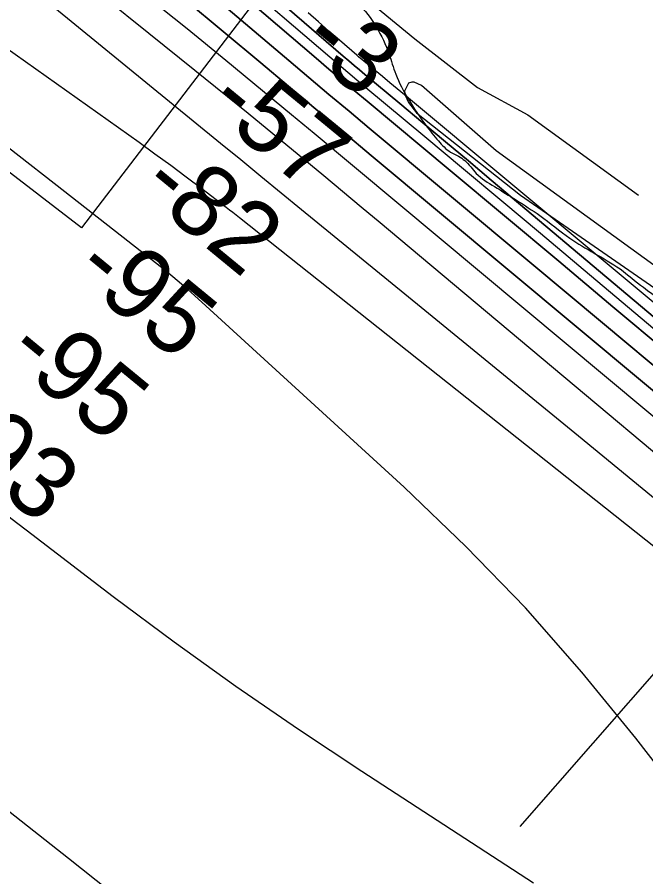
# Model space of a CAD drawing. Extents: x 3887375 to 3925618, y 296674 to 322633.
# Drawn here: x 3894086 to 3894675, y 313327 to 314133 of the extents above; entities that cross this region are included whole.
import ezdxf

# ---------------------------------------------------------------- set-up
doc = ezdxf.new("R2010")
doc.units = 0
for name, color, linetype in [('V-RIVR-EDGE', 7, 'Continuous'), ('V-RIVR-JETY', 7, 'Continuous'), ('V-RIVR-RANG', 7, 'Continuous'), ('V-RRAP-FSHR', 7, 'Continuous'), ('V-RRAP-RVMT', 7, 'Continuous'), ('V-TOPO-DPTH', 7, 'Continuous'), ('V-TOPO-MAJR', 7, 'Continuous'), ('V-TOPO-MINR', 7, 'Continuous')]:
    doc.layers.add(name, color=color, linetype=linetype)

msp = doc.modelspace()

# ---------------------------------------------------------------- linework, layer by layer
at = {"layer": 'V-RIVR-EDGE'}
msp.add_spline([(3894279.09, 314238.38), (3894300.17, 314224.38), (3894318.47, 314210.78), (3894328.81, 314199.99), (3894339.15, 314192.4), (3894356.26, 314181.59), (3894374.58, 314173.98), (3894382.14, 314170.37), (3894386.51, 314164.78), (3894397.24, 314152.8), (3894405.19, 314145.6), (3894434.57, 314098.11), (3894440.9, 314079.36), (3894452.8, 314055.82), (3894469.08, 314031.46), (3894480.99, 314016.69), (3894492.13, 314006.3), (3894499.69, 314002.3), (3894505.66, 313998.3), (3894516.39, 313986.31), (3894533.5, 313973.92), (3894554.19, 313961.11), (3894576.07, 313946.71), (3894604.32, 313925.52), (3894627, 313911.51), (3894651.27, 313896.71), (3894673.15, 313879.52), (3894705.37, 313857.52), (3894744.36, 313828.33), (3894786.92, 313794.75), (3894815.16, 313773.55), (3894843.81, 313753.56), (3894864.49, 313737.96), (3894892.75, 313720.36), (3894906.27, 313709.96), (3894922.58, 313696.37), (3894976.66, 313648.01), (3895020.01, 313612.44), (3895065.34, 313570.88), (3895097.95, 313544.49), (3895112.67, 313532.9), (3895136.93, 313510.92), (3895150.44, 313495.74), (3895161.57, 313484.16), (3895169.53, 313478.16), (3895202.12, 313443.41), (3895238.3, 313409.84), (3895281.24, 313368.29), (3895321.02, 313337.1), (3895346.88, 313317.51), (3895405.32, 313261.97), (3895426, 313241.2), (3895440.7, 313224.82), (3895449.44, 313212.44)], degree=3, dxfattribs=at)
at = {"layer": 'V-RIVR-JETY'}
msp.add_lwpolyline([(3894730.72, 313865.59), (3894535.14, 314007.56), (3894464.91, 314068.73), (3894458.11, 314071.75), (3894455.85, 314071.75), (3894452.82, 314071), (3894449.05, 314063.44), (3894449.8, 314059.67), (3894452.82, 314052.87), (3894460.38, 314043.05), (3894557.79, 313966.03), (3894695.99, 313870.12)], dxfattribs=at)
at = {"layer": 'V-RIVR-RANG'}
msp.add_line((3895031.53, 313915.92), (3894557.25, 313374.2), dxfattribs=at)
at = {"layer": 'V-RRAP-FSHR'}
msp.add_lwpolyline([(3894109.56, 314396.62), (3894271.96, 314268.33), (3894360.72, 314193.19), (3894458.91, 314112.56), (3894517.45, 314066.74), (3894564.66, 314041.08), (3894668.52, 313965.94)], dxfattribs=at)
at = {"layer": 'V-RRAP-RVMT'}
for p, q in [((3894338.29, 314186.44), (3894146.24, 313935.33)), ((3894146.24, 313935.33), (3894046.94, 314011.42))]:
    msp.add_line(p, q, dxfattribs=at)
at = {"layer": 'V-TOPO-DPTH'}
for points in [[(3895305.16, 313270.77), (3895231.56, 313335.34), (3895157.88, 313399.81), (3894995.3, 313541.84), (3894980.78, 313554.46), (3894966.21, 313567.04), (3894951.59, 313579.53), (3894936.92, 313591.98), (3894833.93, 313678.9), (3894767.68, 313734.72), (3894701.37, 313790.45), (3894634.96, 313846.06), (3894568.48, 313901.59), (3894415.94, 314028.77), (3894397.05, 314044.56), (3894378.18, 314060.37), (3894359.34, 314076.22), (3894340.52, 314092.09), (3893865.37, 314493.75)], [(3893865.37, 314493.75), (3894340.52, 314092.09), (3894359.34, 314076.22), (3894378.18, 314060.37), (3894397.05, 314044.56), (3894415.94, 314028.77), (3894568.48, 313901.59), (3894634.96, 313846.06), (3894701.37, 313790.45), (3894767.68, 313734.72), (3894833.93, 313678.9), (3894936.92, 313591.98), (3894951.59, 313579.53), (3894966.21, 313567.04), (3894980.78, 313554.46), (3894995.3, 313541.84), (3895157.88, 313399.81), (3895231.56, 313335.34), (3895305.16, 313270.77)], [(3895236.78, 313307.47), (3895189.92, 313348.65), (3895143.02, 313389.78), (3895096.04, 313430.82), (3895049.01, 313471.8), (3894970.56, 313540.04), (3894962.7, 313546.84), (3894954.82, 313553.63), (3894946.91, 313560.38), (3894938.99, 313567.11), (3894882.83, 313614.59), (3894846.78, 313645.01), (3894810.69, 313675.38), (3894774.54, 313705.68), (3894738.35, 313735.93), (3894417.97, 314003.19), (3894392.02, 314024.83), (3894366.08, 314046.48), (3894340.14, 314068.13), (3894314.2, 314089.78), (3894102.47, 314266.53)], [(3894102.47, 314266.53), (3894314.2, 314089.78), (3894340.14, 314068.13), (3894366.08, 314046.48), (3894392.02, 314024.83), (3894417.97, 314003.19), (3894738.35, 313735.93), (3894774.54, 313705.68), (3894810.69, 313675.38), (3894846.78, 313645.01), (3894882.83, 313614.59), (3894938.99, 313567.11), (3894946.91, 313560.38), (3894954.82, 313553.63), (3894962.7, 313546.84), (3894970.56, 313540.04), (3895049.01, 313471.8), (3895096.04, 313430.82), (3895143.02, 313389.78), (3895189.92, 313348.65), (3895236.78, 313307.47)], [(3894208.2, 314229.17), (3894366.18, 314094.17), (3894378.08, 314084.04), (3894390.01, 314073.95), (3894401.97, 314063.9), (3894413.96, 314053.88), (3894491.91, 313989), (3894542.85, 313946.52), (3894593.74, 313903.97), (3894644.56, 313861.34), (3894695.32, 313818.64), (3894934.83, 313616.82), (3894956.24, 313598.66), (3894977.59, 313580.42), (3894998.83, 313562.05), (3895019.99, 313543.6), (3895384.8, 313223.59)], [(3894208.2, 314229.17), (3894366.18, 314094.17), (3894378.08, 314084.04), (3894390.01, 314073.95), (3894401.97, 314063.9), (3894413.96, 314053.88), (3894491.91, 313989), (3894542.85, 313946.52), (3894593.74, 313903.97), (3894644.56, 313861.34), (3894695.32, 313818.64), (3894934.83, 313616.82), (3894956.24, 313598.66), (3894977.59, 313580.42), (3894998.83, 313562.05), (3895019.99, 313543.6), (3895384.8, 313223.59)], [(3895602.02, 313054.44), (3895044.64, 313545.3), (3895016.85, 313569.61), (3894988.95, 313593.79), (3894960.89, 313617.78), (3894932.72, 313641.65), (3894530.51, 313980.01), (3894509.11, 313997.98), (3894487.68, 314015.92), (3894466.23, 314033.83), (3894444.75, 314051.71), (3894411.96, 314078.96), (3894406.87, 314083.21), (3894401.8, 314087.48), (3894396.75, 314091.78), (3894391.72, 314096.09), (3894339.08, 314141.49)], [(3894339.08, 314141.49), (3894391.72, 314096.09), (3894396.75, 314091.78), (3894401.8, 314087.48), (3894406.87, 314083.21), (3894411.96, 314078.96), (3894444.75, 314051.71), (3894466.23, 314033.83), (3894487.68, 314015.92), (3894509.11, 313997.98), (3894530.51, 313980.01), (3894932.72, 313641.65), (3894960.89, 313617.78), (3894988.95, 313593.79), (3895016.85, 313569.61), (3895044.64, 313545.3), (3895602.02, 313054.44)]]:
    msp.add_lwpolyline(points, dxfattribs=at)
at = {"layer": 'V-TOPO-MAJR'}
msp.add_lwpolyline([(3895553.31, 313005.87), (3894986.85, 313502.45), (3894979.63, 313508.77), (3894972.4, 313515.07), (3894965.16, 313521.37), (3894957.92, 313527.65), (3894945.77, 313538.17), (3894943.41, 313540.21), (3894941.04, 313542.22), (3894932.56, 313549.4), (3894927.13, 313553.99), (3894921.69, 313558.57), (3894916.24, 313563.14), (3894910.79, 313567.7), (3894364.26, 314023.55), (3894359, 314027.93), (3894353.73, 314032.31), (3894348.46, 314036.68), (3894343.18, 314041.04), (3894281.42, 314091.99), (3894245.15, 314121.68), (3894208.72, 314151.19)], dxfattribs=at)
at = {"layer": 'V-TOPO-MINR'}
for points in [[(3892953.66, 314518.69), (3893400.91, 314191.75), (3893432.83, 314168.28), (3893464.67, 314144.7), (3893496.39, 314120.94), (3893528.02, 314097.07), (3893537.4, 314089.96), (3893573.57, 314062.33), (3893609.62, 314034.55), (3893645.49, 314006.54), (3893681.25, 313978.39), (3894026.21, 313704.98), (3894044.41, 313690.64), (3894062.67, 313676.37), (3894081.01, 313662.2), (3894099.4, 313648.1), (3894175.93, 313589.8), (3894233.1, 313547.27), (3894290.88, 313505.62), (3894349.6, 313465.3), (3894408.95, 313425.87), (3894570.06, 313321.43)], [(3895305.16, 313270.77), (3895231.56, 313335.34), (3895157.88, 313399.81), (3894995.3, 313541.84), (3894980.78, 313554.46), (3894966.21, 313567.04), (3894951.59, 313579.53), (3894936.92, 313591.98), (3894833.93, 313678.9), (3894767.68, 313734.72), (3894701.37, 313790.45), (3894634.96, 313846.06), (3894568.48, 313901.59), (3894415.94, 314028.77), (3894397.05, 314044.56), (3894378.18, 314060.37), (3894359.34, 314076.22), (3894340.52, 314092.09), (3893865.37, 314493.75)], [(3895067.88, 313320.76), (3895022.73, 313359.11), (3894977.43, 313397.28), (3894898.35, 313463.48), (3894892.45, 313468.4), (3894886.54, 313473.29), (3894880.61, 313478.16), (3894874.65, 313483), (3894840.99, 313510.29), (3894818.16, 313528.72), (3894795.29, 313547.11), (3894772.37, 313565.43), (3894749.41, 313583.7), (3894294.27, 313944.56), (3894291.14, 313947.03), (3894288, 313949.49), (3894284.85, 313951.93), (3894281.68, 313954.37), (3894259.02, 313971.73), (3894244.46, 313982.76), (3894229.82, 313993.68), (3894215.06, 314004.44), (3894200.22, 314015.1), (3893695.92, 314373.06)], [(3895517.31, 312998.4), (3894948.01, 313464.64), (3894927.73, 313481.26), (3894907.44, 313497.88), (3894887.17, 313514.51), (3894866.89, 313531.15), (3894759.93, 313618.93), (3894686.16, 313679.44), (3894612.35, 313739.9), (3894538.5, 313800.31), (3894464.62, 313860.68), (3894352.53, 313952.21), (3894333.49, 313967.76), (3894314.46, 313983.3), (3894295.43, 313998.84), (3894276.4, 314014.39), (3893851.13, 314361.81)], [(3894770.27, 313317.49), (3894763.49, 313329.15), (3894756.01, 313340.37), (3894748.06, 313351.29), (3894666.09, 313456.8), (3894615.29, 313518.86), (3894562.48, 313579.07), (3894506.67, 313636.5), (3894448.85, 313692.09), (3894255.51, 313868.67), (3894245.73, 313877.4), (3894235.81, 313885.99), (3894225.71, 313894.35), (3894215.48, 313902.56), (3894130.65, 313969.06), (3894077.74, 314010.19), (3894024.6, 314051.01), (3893971.12, 314091.38), (3893917.41, 314131.46), (3893677.86, 314308.63)], [(3895236.78, 313307.47), (3895189.92, 313348.65), (3895143.02, 313389.78), (3895096.04, 313430.82), (3895049.01, 313471.8), (3894970.56, 313540.04), (3894962.7, 313546.84), (3894954.82, 313553.63), (3894946.91, 313560.38), (3894938.99, 313567.11), (3894882.83, 313614.59), (3894846.78, 313645.01), (3894810.69, 313675.38), (3894774.54, 313705.68), (3894738.35, 313735.93), (3894417.97, 314003.19), (3894392.02, 314024.83), (3894366.08, 314046.48), (3894340.14, 314068.13), (3894314.2, 314089.78), (3894102.47, 314266.53)], [(3895384.8, 313223.59), (3895019.99, 313543.6), (3894998.83, 313562.05), (3894977.59, 313580.42), (3894956.24, 313598.66), (3894934.83, 313616.82), (3894695.32, 313818.64), (3894644.56, 313861.34), (3894593.74, 313903.97), (3894542.85, 313946.52), (3894491.91, 313989), (3894413.96, 314053.88), (3894401.97, 314063.9), (3894390.01, 314073.95), (3894378.08, 314084.04), (3894366.18, 314094.17), (3894208.2, 314229.17)], [(3893006.97, 314210.51), (3893277.63, 314013.95), (3893302.99, 313995.36), (3893328.24, 313976.63), (3893353.33, 313957.68), (3893378.31, 313938.59), (3893466.69, 313870.43), (3893535.66, 313816.99), (3893604.46, 313763.34), (3893673.02, 313709.38), (3893741.41, 313655.21), (3893875.6, 313548.42), (3893900.17, 313528.9), (3893924.76, 313509.39), (3893949.37, 313489.92), (3893974, 313470.48), (3894133.94, 313344.36), (3894197.92, 313293.57)], [(3895494.53, 313138.2), (3895032.33, 313544.46), (3895007.85, 313565.83), (3894983.27, 313587.11), (3894958.57, 313608.23), (3894933.77, 313629.24), (3894612.66, 313899.6), (3894576.62, 313929.89), (3894540.54, 313960.13), (3894504.41, 313990.31), (3894468.24, 314020.45), (3894412.96, 314066.42), (3894404.42, 314073.56), (3894395.91, 314080.72), (3894387.43, 314087.92), (3894378.97, 314095.15), (3894287.47, 314173.72)], [(3895172.63, 313313.98), (3895093.31, 313380.93), (3894986.19, 313470.86), (3894956.51, 313495.77), (3894926.82, 313520.68), (3894897.12, 313545.57), (3894867.41, 313570.46), (3894443.8, 313925.24), (3894426.2, 313939.97), (3894408.58, 313954.68), (3894390.95, 313969.37), (3894373.3, 313984.04), (3894355.62, 313998.67), (3894337.9, 314013.26), (3894320.14, 314027.78), (3894302.34, 314042.27), (3894252.33, 314082.81), (3894209.43, 314117.45), (3894166.43, 314151.96)], [(3895602.02, 313054.44), (3895044.64, 313545.3), (3895016.85, 313569.61), (3894988.95, 313593.79), (3894960.89, 313617.78), (3894932.72, 313641.65), (3894530.51, 313980.01), (3894509.11, 313997.98), (3894487.68, 314015.92), (3894466.23, 314033.83), (3894444.75, 314051.71), (3894411.96, 314078.96), (3894406.87, 314083.21), (3894401.8, 314087.48), (3894396.75, 314091.78), (3894391.72, 314096.09), (3894339.08, 314141.49)], [(3895329.44, 313320.08), (3895274.25, 313367.53), (3895218.98, 313414.89), (3895163.6, 313462.12), (3895108.14, 313509.25), (3895062.71, 313547.76), (3895029.87, 313575.52), (3894996.98, 313603.23), (3894964.02, 313630.85), (3894931.01, 313658.42), (3894449, 314059.86), (3894442.12, 314065.6), (3894435.23, 314071.32), (3894428.34, 314077.05), (3894421.45, 314082.77), (3894410.95, 314091.49), (3894409.31, 314092.86), (3894406.06, 314095.62), (3894404.45, 314097.01), (3894388.05, 314111.21), (3894378.23, 314119.7), (3894368.41, 314128.19), (3894358.58, 314136.66)]]:
    msp.add_lwpolyline(points, dxfattribs=at)

# ---------------------------------------------------------------- texts
at = {"layer": 'V-RIVR-RANG'}
for s, rotation, p in [('-3', 320.29833, (3894348.68, 314105.19)), ('-57', 320.58558, (3894261.32, 314047.2)), ('-82', 320.58558, (3894198.45, 313969.43)), ('-95', 320.58558, (3894136.4, 313890.99)), ('-95', 320.58558, (3894072.72, 313813.89)), ('-93', 320.58558, (3894007.81, 313737.8))]:
    msp.add_text(s, height=67, rotation=rotation, dxfattribs=at).set_placement(p)

doc.saveas('drawing.dxf')
